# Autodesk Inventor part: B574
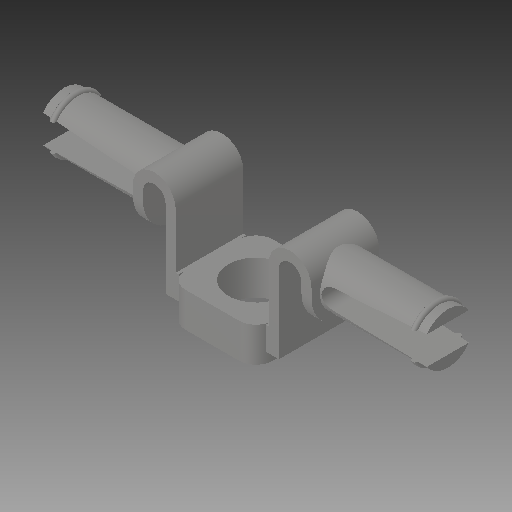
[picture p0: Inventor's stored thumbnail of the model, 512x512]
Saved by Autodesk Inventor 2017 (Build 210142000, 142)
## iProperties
Part Number: B574
Material: Générique
Document SubType Name: Modeling
Designer: ficho
Density: 1 g/cm^3
Appearance: Par défaut
Author: ficho
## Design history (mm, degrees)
feature "Solid1"
node "Solide1"
